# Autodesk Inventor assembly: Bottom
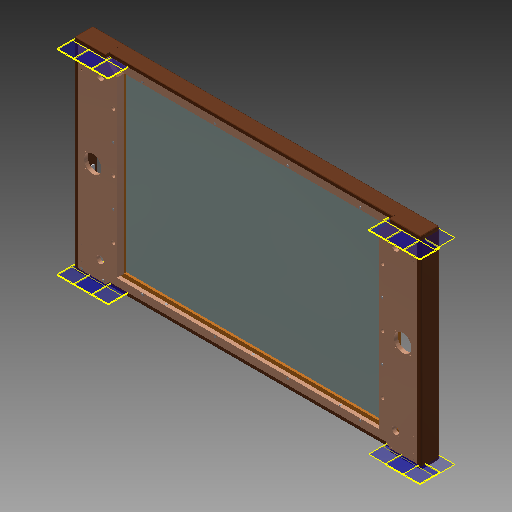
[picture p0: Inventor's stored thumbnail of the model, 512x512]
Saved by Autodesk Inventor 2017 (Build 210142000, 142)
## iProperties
Created: 2017-05
Part Number: Bottom
Document SubType Name: Assembly
Designer: Savy
Author: Savy
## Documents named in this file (20)
- D:\Users\Savy\Documents\Infinity Table\Bottom.iam
- D:\Users\Savy\Documents\Infinity Table\BottomInnerPanel_Long.ipt
- D:\Users\Savy\Documents\Infinity Table\BottomInnerPanel_Short.ipt
- D:\Users\Savy\Documents\Infinity Table\Mirror.ipt
- D:\Users\Savy\Documents\Infinity Table\BottomInnerSpacer_Long.ipt
- D:\Users\Savy\Documents\Infinity Table\BottomInnerSpacer_Short.ipt
- D:\Users\Savy\Documents\Infinity Table\BottomBase_Short.ipt
- D:\Users\Savy\Documents\Infinity Table\BottomSide_Long1.ipt
- D:\Users\Savy\Documents\Infinity Table\BottomSide_Long2.ipt
- D:\Users\Savy\Documents\Infinity Table\PSU_AC.ipt
- D:\Users\Savy\Documents\Infinity Table\USBPorts.ipt
- D:\Users\Savy\Documents\Infinity Table\ChannelAssembly.iam
- D:\Users\Savy\Documents\Infinity Table\USBMount.ipt
- D:\Users\Savy\Documents\Infinity Table\8_Screw_1inch.ipt
- D:\Users\Savy\Documents\Infinity Table\8_Screw_1-25inch.ipt
- D:\Users\Savy\Documents\Infinity Table\8_Screw_-5inch.ipt
- D:\Users\Savy\Documents\Infinity Table\BottomSide_Short.ipt
- D:\Users\Savy\Documents\Infinity Table\90DegBracket.ipt
- D:\Users\Savy\Documents\Infinity Table\LBracket.ipt
- D:\Users\Savy\Documents\Infinity Table\Magnet.ipt
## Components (130 placed, 107 different names)
1. BottomInnerPanel_Long_1177
2. BottomInnerPanel_Short_1178
3. BottomInnerPanel_Long_1179
4. BottomInnerPanel_Short_1180
5. Mirror_1181
6. BottomInnerSpacer_Long_1182
7. BottomInnerSpacer_Short_1183
8. BottomInnerSpacer_Long_1184
9. BottomInnerSpacer_Short_1185
10. BottomBase_Short_1186
11. BottomBase_Short_1187
12. BottomSide_Long1_1188 — Flush:1, Mate:1, Mate:2, Mate:3, Mate:5
13. BottomSide_Long1_1189 — Mate:19, Mate:20, Mate:21, Mate:22, Mate:23
14. BottomSide_Long1_1190 — Mate:13, Mate:14, Mate:15, Mate:16
15. BottomSide_Long1_1191 — Mate:7, Mate:8, Mate:9, Mate:10
16. BottomSide_Long2_1192
17. BottomSide_Long2_1193
18. PSU_AC_1194
19. PSU_AC_1195
20. USBPorts_1196
21. USBPorts_1197
22. ChannelAssembly_1198 [sub-assembly]
23. USBMount_1199
24. USBMount_1200
25. 8_Screw_1inch_1201
26. 8_Screw_1inch_1202
27. 8_Screw_1inch_1203
28. 8_Screw_1inch_1204
29. 8_Screw_1inch_1205
30. 8_Screw_1inch_1206
31. 8_Screw_1-25inch_1207
32. 8_Screw_1-25inch_1208
33. 8_Screw_1-25inch_1209
34. 8_Screw_1-25inch_1210
35. 8_Screw_1-25inch_1211
36. 8_Screw_1-25inch_1212
37. 8_Screw_1-25inch_1213
38. 8_Screw_1-25inch_1214
39. 8_Screw_1-25inch_1215
40. 8_Screw_1-25inch_1216
41. 8_Screw_1-25inch_1217
42. 8_Screw_1-25inch_1218
43. 8_Screw_1-25inch_1219
44. 8_Screw_1-25inch_1220
45. 8_Screw_1-25inch_1221
46. 8_Screw_1-25inch_1222
47. 8_Screw_1-25inch_1223
48. 8_Screw_1-25inch_1224
49. 8_Screw_1-25inch_1225
50. 8_Screw_1-25inch_1226
51. 8_Screw_1inch_1227
52. 8_Screw_1inch_1228
53. 8_Screw_1inch_1229
54. 8_Screw_1inch_1230
55. 8_Screw_-5inch_1231
56. 8_Screw_-5inch_1232
57. 8_Screw_-5inch_1233
58. 8_Screw_-5inch_1234
59. 8_Screw_-5inch_1235
60. 8_Screw_-5inch_1236
61. 8_Screw_-5inch_1237
62. 8_Screw_-5inch_1238
63. BottomSide_Short_1247
64. BottomSide_Short_1248
65. 90DegBracket_1249
66. 90DegBracket_1250
67. 90DegBracket_1251
68. 90DegBracket_1252
69. 90DegBracket_1253
70. 90DegBracket_1254
71. 90DegBracket_1255
72. 90DegBracket_1256
73. 90DegBracket_1257
74. 90DegBracket_1258
75. 8_Screw_-5inch_1259
76. 8_Screw_-5inch_1260
77. 8_Screw_-5inch_1261
78. 8_Screw_-5inch_1262
79. 8_Screw_-5inch_1263
80. 8_Screw_-5inch_1264
81. 8_Screw_-5inch_1265
82. 8_Screw_-5inch_1266
83. 8_Screw_-5inch_1267
84. 8_Screw_-5inch_1268
85. 8_Screw_-5inch_1269
86. 8_Screw_-5inch_1270
87. 8_Screw_-5inch_1271
88. 8_Screw_-5inch_1272
89. 8_Screw_-5inch_1273
90. 8_Screw_-5inch_1274
91. 8_Screw_-5inch_1275
92. 8_Screw_-5inch_1276
93. 8_Screw_-5inch_1277
94. 8_Screw_-5inch_1278
95. LBracket_1279
96. LBracket_1280
97. LBracket_1281
98. LBracket_1282
99. 8_Screw_-5inch_1283
100. 8_Screw_-5inch_1284
101. 8_Screw_-5inch_1285
102. 8_Screw_-5inch_1286
103. 8_Screw_-5inch_1287
104. 8_Screw_-5inch_1288
105. 8_Screw_-5inch_1289
106. 8_Screw_-5inch_1290
107. Magnet:1 — Flush:1
108. Magnet:2 — Mate:1
109. Magnet:3 — Mate:4
110. Magnet:7 — Mate:3, Mate:4
111. Magnet:8 — Mate:5
112. Magnet:9 — Mate:2
113. Magnet:10 — Mate:8
114. Magnet:11 — Mate:7
115. Magnet:12
116. Magnet:13 — Mate:9
117. Magnet:14 — Mate:11
118. Magnet:15 — Mate:10, Mate:11
119. Magnet:16 — Mate:14
120. Magnet:17 — Mate:13
121. Magnet:18
122. Magnet:19 — Mate:15
123. Magnet:20 — Mate:17
124. Magnet:21 — Mate:16, Mate:17
125. Magnet:22 — Mate:20
126. Magnet:23 — Mate:19
127. Magnet:24
128. Magnet:25 — Mate:21
129. Magnet:26 — Mate:23
130. Magnet:27 — Mate:22
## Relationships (21: Mate 20, Flush 1)
- Flush:1: BottomSide_Long1_1188 ↔ Magnet:1
- Mate:1: BottomSide_Long1_1188 ↔ Magnet:2
- Mate:2: BottomSide_Long1_1188 ↔ Magnet:9
- Mate:3: BottomSide_Long1_1188 ↔ Magnet:7
- Mate:4: Magnet:3 ↔ Magnet:7
- Mate:5: BottomSide_Long1_1188 ↔ Magnet:8
- Mate:7: BottomSide_Long1_1191 ↔ Magnet:11
- Mate:8: BottomSide_Long1_1191 ↔ Magnet:10
- Mate:9: BottomSide_Long1_1191 ↔ Magnet:13
- Mate:10: BottomSide_Long1_1191 ↔ Magnet:15
- Mate:11: Magnet:14 ↔ Magnet:15
- Mate:13: BottomSide_Long1_1190 ↔ Magnet:17
- Mate:14: BottomSide_Long1_1190 ↔ Magnet:16
- Mate:15: BottomSide_Long1_1190 ↔ Magnet:19
- Mate:16: BottomSide_Long1_1190 ↔ Magnet:21
- Mate:17: Magnet:20 ↔ Magnet:21
- Mate:19: BottomSide_Long1_1189 ↔ Magnet:23
- Mate:20: BottomSide_Long1_1189 ↔ Magnet:22
- Mate:21: BottomSide_Long1_1189 ↔ Magnet:25
- Mate:22: BottomSide_Long1_1189 ↔ Magnet:27
- Mate:23: BottomSide_Long1_1189 ↔ Magnet:26
## Named parameters: d6_d4 = 0, d12_d4 = 0, d18_d4 = 0
